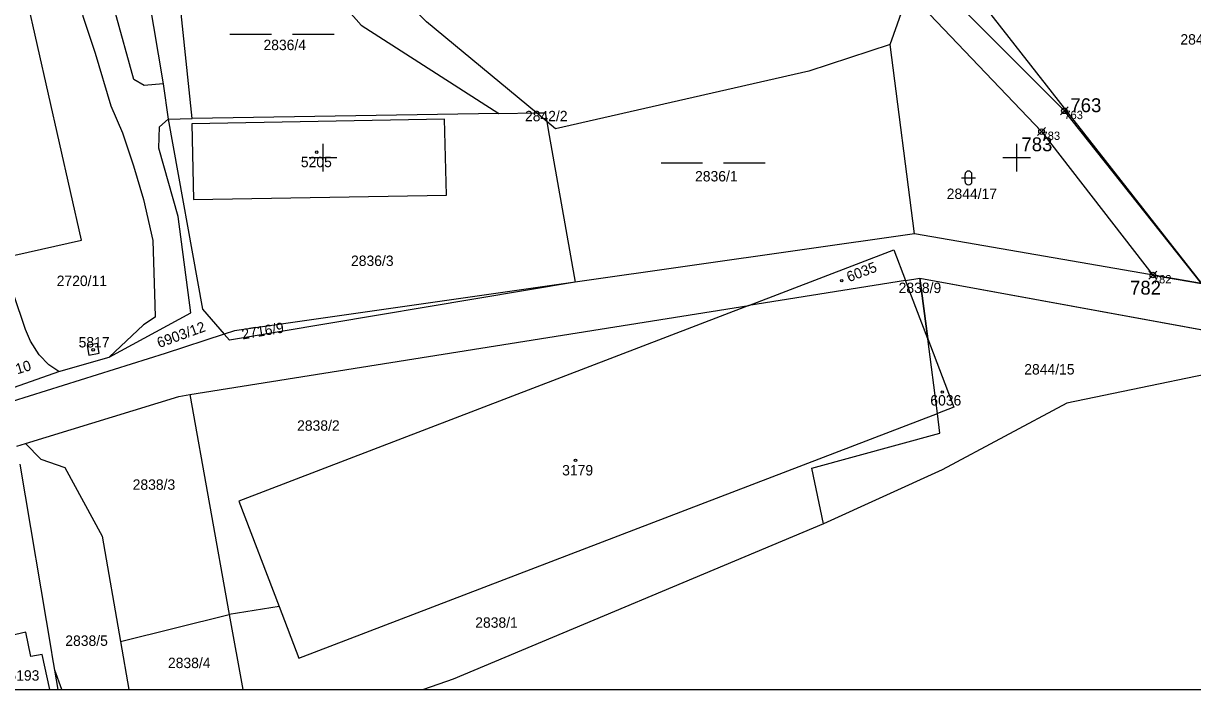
# Model space of a CAD drawing. Extents: x -800194 to -799078, y -1007177 to -1006597.
# Drawn here: x -799843.2 to -799674.6, y -1007176.6 to -1007080.7 of the extents above; entities that cross this region are included whole.
import ezdxf

# ---------------------------------------------------------------- set-up
doc = ezdxf.new("R2010")
doc.units = 0
for name, color, linetype in [('Legenda 1', 7, 'Continuous'), ('Obvod stavby', 7, 'Continuous'), ('Ramove udaje', 7, 'Continuous'), ('Vrstva 53', 7, 'Continuous'), ('Vrstva 55', 7, 'Continuous'), ('Vrstva 57', 7, 'Continuous'), ('Vrstva 58', 7, 'Continuous'), ('Vrstva 59', 7, 'Continuous'), ('Vrstva 60', 7, 'Continuous')]:
    doc.layers.add(name, color=color, linetype=linetype)

msp = doc.modelspace()

# ---------------------------------------------------------------- linework, layer by layer
at = {"layer": 'Legenda 1'}
msp.add_lwpolyline([(-800193.4, -1007176.65), (-799312.4, -1007176.65), (-799312.4, -1006766.65), (-800193.4, -1006766.65)], close=True, dxfattribs=at)
at = {"layer": 'Obvod stavby'}
for p, q in [((-799693.67, -1007093.81), (-799692.54, -1007092.68)), ((-799693.67, -1007092.68), (-799692.54, -1007093.81)), ((-799696.96, -1007096.81), (-799695.83, -1007095.68)), ((-799696.96, -1007095.68), (-799695.83, -1007096.81)), ((-799680.91, -1007117.49), (-799679.78, -1007116.36)), ((-799680.91, -1007116.36), (-799679.78, -1007117.49))]:
    msp.add_line(p, q, dxfattribs=at)
msp.add_lwpolyline([(-799715.54, -1007076.14), (-799696.4, -1007096.25), (-799680.35, -1007116.92), (-799673.33, -1007118.14), (-799693.11, -1007093.25), (-799714.14, -1007072.19)], dxfattribs=at)
for centre in [(-799693.11, -1007093.25), (-799696.4, -1007096.25), (-799680.35, -1007116.92)]:
    msp.add_circle(centre, 0.4, dxfattribs=at)
at = {"layer": 'Ramove udaje'}
for p, q in [((-799800, -1007098), (-799800, -1007102)), ((-799700, -1007098), (-799700, -1007102)), ((-799802, -1007100), (-799800, -1007100)), ((-799800, -1007100), (-799798, -1007100)), ((-799702, -1007100), (-799700, -1007100)), ((-799700, -1007100), (-799698, -1007100))]:
    msp.add_line(p, q, dxfattribs=at)
at = {"layer": 'Vrstva 53'}
for points in [[(-799673.33, -1007118.14), (-799714.71, -1007110.97), (-799718.21, -1007083.69), (-799729.93, -1007087.54), (-799766.47, -1007095.84), (-799767.73, -1007094.8), (-799769.22, -1007093.56), (-799785.06, -1007080.42), (-799809.11, -1007056.81), (-799818.59, -1007034.4), (-799822.79, -1007029.13), (-799826.14, -1007024.13), (-799830.75, -1006966.73), (-799839.73, -1006961.33), (-799877.87, -1006942.17), (-799936.47, -1006903.99), (-799954.76, -1006895.45), (-799964.79, -1006890.84)], [(-799662.13, -1007129.03), (-799692.74, -1007135.4), (-799710.71, -1007144.99), (-799727.84, -1007152.76), (-799729.51, -1007144.72), (-799711.04, -1007139.72), (-799711.41, -1007136.88), (-799712.8, -1007126.1), (-799713.93, -1007117.37), (-799664.74, -1007126.35)]]:
    msp.add_lwpolyline(points, dxfattribs=at)
at = {"layer": 'Vrstva 55'}
for p, q in [((-799818.85, -1007094.38), (-799825.16, -1007033.58)), ((-799718.21, -1007083.69), (-799712.65, -1007067.97)), ((-799712.65, -1007067.97), (-799673.33, -1007118.14)), ((-799714.71, -1007110.97), (-799718.21, -1007083.69)), ((-799823.03, -1007089.38), (-799822.31, -1007094.44)), ((-799822.31, -1007094.44), (-799818.85, -1007094.38)), ((-799774.66, -1007093.65), (-799818.85, -1007094.38)), ((-799774.66, -1007093.65), (-799769.22, -1007093.56)), ((-799767.73, -1007094.8), (-799769.22, -1007093.56)), ((-799714.71, -1007110.97), (-799763.63, -1007117.94)), ((-799673.33, -1007118.14), (-799714.71, -1007110.97)), ((-799716.02, -1007117.7), (-799738.61, -1007121.3)), ((-799716.02, -1007117.7), (-799713.93, -1007117.37)), ((-799712.8, -1007126.1), (-799716.02, -1007117.7)), ((-799713.93, -1007117.37), (-799664.74, -1007126.35)), ((-799713.93, -1007117.37), (-799712.8, -1007126.1)), ((-799819.2, -1007134.15), (-799738.61, -1007121.3)), ((-799711.41, -1007136.88), (-799712.8, -1007126.1)), ((-799838.05, -1007130.83), (-799830.82, -1007128.75)), ((-799853.69, -1007136.27), (-799838.05, -1007130.83)), ((-799819.2, -1007134.15), (-799813.5, -1007165.83)), ((-799803.46, -1007172.11), (-799711.41, -1007136.88)), ((-799844.11, -1007141.59), (-799842.89, -1007141.21)), ((-799842.89, -1007141.21), (-799840.66, -1007143.43)), ((-799727.84, -1007152.76), (-799781.23, -1007175.14)), ((-799831.81, -1007154.54), (-799829.18, -1007169.73)), ((-799806.31, -1007164.66), (-799813.5, -1007165.83)), ((-799806.31, -1007164.66), (-799803.46, -1007172.11)), ((-799829.18, -1007169.73), (-799813.5, -1007165.83)), ((-799813.5, -1007165.83), (-799811.57, -1007176.65)), ((-799829.18, -1007169.73), (-799827.98, -1007176.65)), ((-799837.65, -1007176.65), (-799838.65, -1007173.83)), ((-799781.23, -1007175.14), (-799785.48, -1007176.65))]:
    msp.add_line(p, q, dxfattribs=at)
for points in [[(-799769.22, -1007093.56), (-799785.06, -1007080.42), (-799809.11, -1007056.81), (-799818.59, -1007034.4), (-799822.79, -1007029.13)], [(-799825.16, -1007033.58), (-799811.39, -1007061.77), (-799794.49, -1007080.93), (-799774.66, -1007093.65)], [(-799823.03, -1007089.38), (-799825.77, -1007089.63), (-799827.26, -1007088.72), (-799830.02, -1007078.85), (-799832.03, -1007070.18), (-799833.02, -1007058.82), (-799832.71, -1007046.42)], [(-799831.14, -1007046.62), (-799828.75, -1007046.93), (-799828.27, -1007056.97), (-799826.13, -1007070.87), (-799825.16, -1007076.77), (-799823.03, -1007089.38)], [(-799858.84, -1007065.67), (-799858.76, -1007060.77), (-799858.72, -1007059.86), (-799857.59, -1007058.97), (-799845.38, -1007056.13), (-799841.77, -1007056.79), (-799839.5, -1007058.21), (-799837.43, -1007060.68), (-799836.99, -1007067.77), (-799836.14, -1007072.71), (-799834.61, -1007079.6), (-799832.83, -1007084.94), (-799830.58, -1007092.52), (-799828.9, -1007096.44), (-799827.32, -1007101.2), (-799825.89, -1007106.02), (-799824.52, -1007111.92), (-799824.25, -1007121.19), (-799824.17, -1007122.98), (-799825.87, -1007124.09), (-799830.82, -1007128.75)], [(-799846.34, -1007114.47), (-799834.79, -1007111.87), (-799845.89, -1007062.76), (-799858.84, -1007065.67)], [(-799718.21, -1007083.69), (-799729.93, -1007087.54), (-799766.47, -1007095.84), (-799767.73, -1007094.8)], [(-799830.82, -1007128.75), (-799819.06, -1007122.35), (-799820.88, -1007108.46), (-799823.65, -1007098.62), (-799823.55, -1007095.54), (-799822.31, -1007094.44)], [(-799822.31, -1007094.44), (-799817.36, -1007121.82), (-799814.24, -1007125.43)], [(-799782.48, -1007094.48), (-799818.89, -1007095.11), (-799818.65, -1007106.02), (-799782.2, -1007105.4), (-799782.48, -1007094.48)], [(-799769.22, -1007093.56), (-799767.95, -1007093.54), (-799767.73, -1007094.8)], [(-799767.73, -1007094.8), (-799767.52, -1007095.98), (-799763.63, -1007117.94)], [(-799738.61, -1007121.3), (-799717.71, -1007113.29), (-799716.02, -1007117.7)], [(-799838.05, -1007130.83), (-799839.52, -1007129.85), (-799840.91, -1007128.4), (-799842.17, -1007126.45), (-799842.9, -1007124.78), (-799846.34, -1007114.47)], [(-799763.63, -1007117.94), (-799813.49, -1007126.3), (-799814.24, -1007125.43)], [(-799763.63, -1007117.94), (-799812.76, -1007124.95), (-799814.24, -1007125.43)], [(-799738.61, -1007121.3), (-799812.11, -1007149.49), (-799806.31, -1007164.66)], [(-799814.24, -1007125.43), (-799822.76, -1007128.21), (-799844.82, -1007135.16), (-799895.02, -1007147.45)], [(-799832.49, -1007126.78), (-799834.01, -1007127.06), (-799833.76, -1007128.46), (-799832.24, -1007128.15), (-799832.49, -1007126.78)], [(-799712.8, -1007126.1), (-799709.02, -1007135.97), (-799711.41, -1007136.88)], [(-799662.13, -1007129.03), (-799692.74, -1007135.4), (-799710.71, -1007144.99), (-799727.84, -1007152.76)], [(-799842.89, -1007141.21), (-799820.76, -1007134.4), (-799819.2, -1007134.15)], [(-799727.84, -1007152.76), (-799729.51, -1007144.72), (-799711.04, -1007139.72), (-799711.41, -1007136.88)], [(-799840.66, -1007143.43), (-799837.23, -1007144.63), (-799831.81, -1007154.54)], [(-799838.65, -1007173.83), (-799839.02, -1007171.64), (-799839.09, -1007171.24), (-799843.67, -1007144.18)], [(-799839.36, -1007176.65), (-799840.49, -1007171.57), (-799842.09, -1007171.9), (-799842.85, -1007168.35), (-799846.6, -1007169.23), (-799847.19, -1007169.37), (-799847.51, -1007167.75), (-799861.36, -1007170.85), (-799866.14, -1007171.83), (-799865.33, -1007175.48), (-799865.03, -1007176.65)], [(-799838.17, -1007176.65), (-799838.65, -1007173.83)]]:
    msp.add_lwpolyline(points, dxfattribs=at)
at = {"layer": 'Vrstva 58'}
for p, q in [((-799813.4, -1007082.19), (-799807.4, -1007082.19)), ((-799804.4, -1007082.19), (-799798.4, -1007082.19)), ((-799751.26, -1007100.77), (-799745.26, -1007100.77)), ((-799742.26, -1007100.77), (-799736.26, -1007100.77)), ((-799707.94, -1007102.93), (-799705.93, -1007102.93)), ((-799707.44, -1007102.43), (-799707.44, -1007103.43)), ((-799706.43, -1007103.43), (-799706.43, -1007102.43))]:
    msp.add_line(p, q, dxfattribs=at)
for centre, start, end in [((-799706.93, -1007102.43), 0, 180), ((-799706.93, -1007103.43), 180, 359.9879)]:
    msp.add_arc(centre, 0.5, start, end, dxfattribs=at)
at = {"layer": 'Vrstva 59'}
for centre in [(-799800.9, -1007099.21), (-799725.21, -1007117.73), (-799833.12, -1007127.69), (-799710.71, -1007133.78), (-799763.59, -1007143.63)]:
    msp.add_circle(centre, 0.175, dxfattribs=at)
at = {"layer": 'Vrstva 60'}
for p, q in [((-799693.11, -1007093.25), (-799693.11, -1007093.25)), ((-799696.4, -1007096.25), (-799696.4, -1007096.25)), ((-799680.35, -1007116.92), (-799680.35, -1007116.92))]:
    msp.add_line(p, q, dxfattribs=at)

# ---------------------------------------------------------------- texts
at = {"layer": 'Obvod stavby'}
for s, p in [('763', (-799692.24, -1007093.45)), ('783', (-799699.3, -1007099.08)), ('782', (-799683.64, -1007119.74))]:
    msp.add_text(s, height=2, rotation=360, dxfattribs=at).set_placement(p)
at = {"layer": 'Vrstva 57'}
for s, p in [('2836/4', (-799808.57, -1007084.51)), ('2844/77', (-799676.38, -1007083.71)), ('2842/2', (-799770.87, -1007094.76)), ('5205', (-799803.18, -1007101.38)), ('2836/1', (-799746.35, -1007103.43)), ('2844/17', (-799710.07, -1007105.96)), ('2836/3', (-799795.95, -1007115.61)), ('2720/11', (-799838.38, -1007118.5)), ('2838/9', (-799717, -1007119.51)), ('5817', (-799835.22, -1007127.35)), ('2844/15', (-799698.89, -1007131.25)), ('6036', (-799712.43, -1007135.72)), ('2838/2', (-799803.72, -1007139.35)), ('3179', (-799765.51, -1007145.79)), ('2838/3', (-799827.43, -1007147.86)), ('2838/1', (-799778.04, -1007167.74)), ('2838/5', (-799837.14, -1007170.35)), ('2838/4', (-799822.34, -1007173.55)), ('5193', (-799845.34, -1007175.36))]:
    msp.add_text(s, height=1.5, dxfattribs=at).set_placement(p)
for s, rotation, p in [('6035', 21, (-799724.15, -1007117.96)), ('6903/12', 20, (-799823.6, -1007127.45)), ('2716/9', 9.6773, (-799811.58, -1007126.21)), ('2720/10', 17, (-799848.86, -1007132.7))]:
    msp.add_text(s, height=1.5, rotation=rotation, dxfattribs=at).set_placement(p)
at = {"layer": 'Vrstva 60'}
for s, p in [('763', (-799693.11, -1007094.45)), ('783', (-799696.4, -1007097.45)), ('782', (-799680.35, -1007118.12))]:
    msp.add_text(s, height=1.2, dxfattribs=at).set_placement(p)

doc.saveas('drawing.dxf')
